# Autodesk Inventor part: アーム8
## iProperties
Created: 2008-02
Part Number: アーム8
Document SubType Name: Modeling
Designer: y-shimazaki
Density: 1 g/cm^3
Author: y-shimazaki
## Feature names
1. 押し出し1 [Extrusion]
2. 押し出し2 [Extrusion]
3. ミラー1 [Mirror]
4. 押し出し3 [Extrusion]
